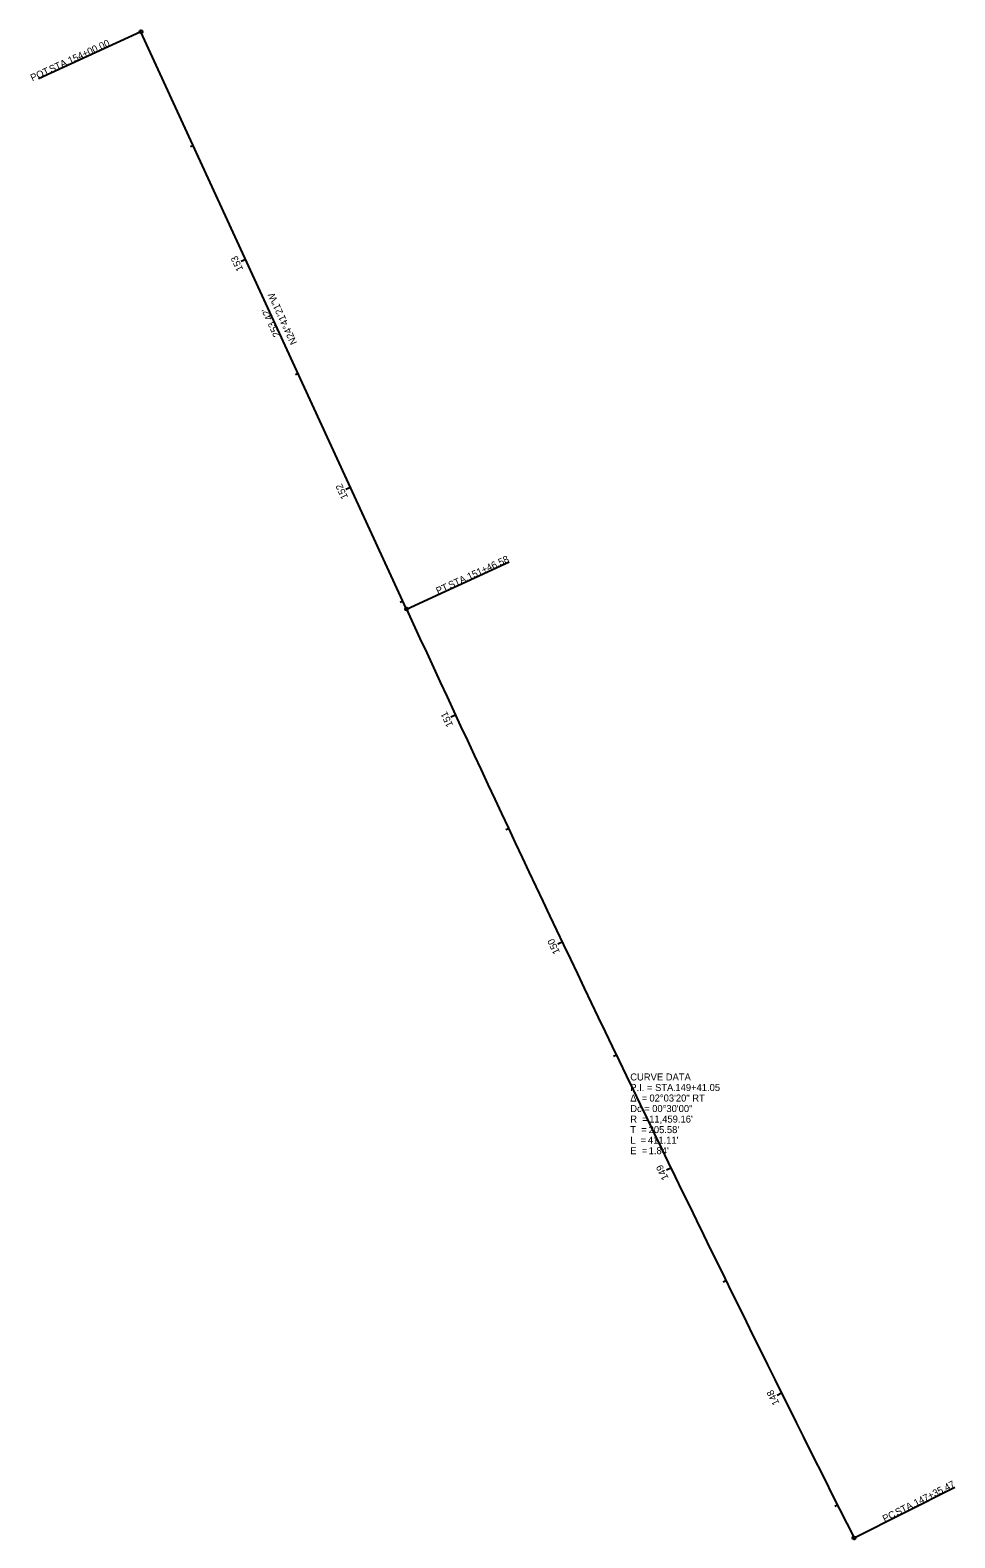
# Model space of a CAD drawing. Extents: x 1359387 to 1360093, y 668188 to 669559.
# Drawn here: x 1359387 to 1359756, y 668957 to 669559 of the extents above; entities that cross this region are included whole.
import ezdxf

# ---------------------------------------------------------------- set-up
doc = ezdxf.new("R2010")
doc.units = 0
for name, color, linetype in [('_CIVIL_CONSTRUCTION', 7, 'Continuous'), ('Default', 7, 'Continuous'), ('SH_Border', 7, 'Continuous'), ('SH_Data', 7, 'Continuous'), ('SH_Major_Grid_Line', 7, 'Continuous'), ('SH_Named_Boundary', 7, 'Continuous'), ('SH_Text', 7, 'Continuous')]:
    doc.layers.add(name, color=color, linetype=linetype)

msp = doc.modelspace()

# ---------------------------------------------------------------- linework, layer by layer
at = {"layer": 'Default'}
msp.add_line((1359537.11, 669327.68), (1359431.26, 669557.93), dxfattribs=at)
msp.add_arc((1369948.76, 674114.1), 11459.16, 204.689088, 206.744644, dxfattribs=at)
at = {"layer": 'SH_Data'}
for p, q in [((1359431.26, 669557.93), (1359390.37, 669539.14)), ((1359537.11, 669327.68), (1359577.99, 669346.48)), ((1359715.49, 668957.31), (1359755.68, 668977.56))]:
    msp.add_line(p, q, dxfattribs=at)
for centre in [(1359431.26, 669557.93), (1359537.11, 669327.68), (1359715.49, 668957.31)]:
    msp.add_circle(centre, 0.6, dxfattribs=at)
at = {"layer": 'SH_Named_Boundary'}
msp.add_line((1359537.11, 669327.68), (1359431.26, 669557.93), dxfattribs=at)
msp.add_arc((1369948.76, 674114.1), 11459.16, 204.689088, 206.744644, dxfattribs=at)
at = {"layer": 'SH_Text'}
for p, q in [((1359452.14, 669512.5), (1359451.05, 669512)), ((1359473.03, 669467.08), (1359471.21, 669466.24)), ((1359493.91, 669421.65), (1359492.82, 669421.14)), ((1359514.79, 669376.22), (1359512.98, 669375.38)), ((1359535.68, 669330.79), (1359534.59, 669330.29)), ((1359556.65, 669285.4), (1359554.84, 669284.55)), ((1359577.82, 669240.1), (1359576.73, 669239.59)), ((1359599.18, 669194.89), (1359597.38, 669194.04)), ((1359620.75, 669149.78), (1359619.66, 669149.26)), ((1359642.51, 669104.77), (1359640.71, 669103.89)), ((1359664.46, 669059.84), (1359663.38, 669059.31)), ((1359686.61, 669015.02), (1359684.82, 669014.13)), ((1359708.96, 668970.29), (1359707.89, 668969.75))]:
    msp.add_line(p, q, dxfattribs=at)

# ---------------------------------------------------------------- texts
at = {"layer": '_CIVIL_CONSTRUCTION'}
msp.add_text("253.42'", height=2.8, rotation=114.68909, dxfattribs=at).set_placement((1359486.84, 669436.94))
at = {"layer": 'SH_Border'}
msp.add_text('N24°41\'21"W', height=2.8, rotation=114.68909, dxfattribs=at).set_placement((1359493.57, 669433.88))
at = {"layer": 'SH_Data'}
for s, rotation, p in [('154+00.00', 24.68909, (1359402.94, 669544.96)), ('POT', 24.68909, (1359387.99, 669538.08)), (' STA. ', 24.68909, (1359394.47, 669541.06)), ('151+46.58', 24.68909, (1359562.06, 669339.19)), ('PT', 24.68909, (1359549.64, 669333.48)), (' STA. ', 24.68909, (1359553.59, 669335.3)), ('147+35.47', 26.74464, (1359740.13, 668969.77)), (' STA. ', 26.74464, (1359731.8, 668965.57)), ('PC', 26.74464, (1359727.7, 668963.5))]:
    msp.add_text(s, height=2.8, rotation=rotation, dxfattribs=at).set_placement(p)
at = {"layer": 'SH_Major_Grid_Line'}
for s, p in [('CURVE DATA', (1359626.3, 669139.7)), ('Δ  = ', (1359626.3, 669131.3)), ('P.I. = STA. ', (1359626.3, 669135.5)), ('02°03\'20" RT', (1359633.94, 669131.3)), ('149+41.05', (1359644.29, 669135.5)), ('Dc = ', (1359626.3, 669127.1)), ('00°30\'00"', (1359635.04, 669127.1)), ('T  = ', (1359626.3, 669118.7)), ('R  = ', (1359626.3, 669122.9)), ("205.58'", (1359633.62, 669118.7)), ("11,459.16'", (1359633.83, 669122.9)), ('L  = ', (1359626.3, 669114.5)), ("411.11'", (1359633.33, 669114.5)), ('E  = ', (1359626.3, 669110.3)), ("1.84'", (1359633.64, 669110.3))]:
    msp.add_text(s, height=2.8, dxfattribs=at).set_placement(p)
at = {"layer": 'SH_Text'}
for s, rotation, p in [('153', 114.68909, (1359472.09, 669463.13)), ('152', 114.68909, (1359513.86, 669372.25)), ('151', 114.92199, (1359555.74, 669281.42)), ('150', 115.42199, (1359598.33, 669190.87)), ('149', 115.92199, (1359641.67, 669100.77)), ('148', 116.42199, (1359685.82, 669011))]:
    msp.add_text(s, height=2.8, rotation=rotation, dxfattribs=at).set_placement(p)

doc.saveas('drawing.dxf')
